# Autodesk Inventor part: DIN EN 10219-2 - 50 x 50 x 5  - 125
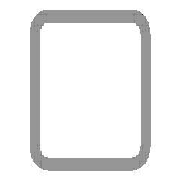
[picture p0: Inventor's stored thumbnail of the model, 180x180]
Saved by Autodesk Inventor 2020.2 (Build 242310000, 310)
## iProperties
Created: 2019-11
Part Number: DIN EN 10219-2 - 50 x 50 x 5  - 125
Material: Generisch
Description: Kaltgeformte, geschweißte Baustahl-Hohlprofile aus unlegiertem Feinkorn-Baustahl
Document SubType Name: Modeling
Standard: DIN
Designer: lutzd
Standard Revision: 2006-07
Standards Organization: DIN
Language: de-DE
Size Designation: 50 x 50 x 5
Categories: <MemberInstance><Categories><Category DisplayName="Profile" InternalName="089c4875-fa83-4c05-b084-43b9cc11f5ed" Mnemonic="GRDR"><CategoryParameter DisplayName="
Stock Number: 50 x 50 x 5
Mass: 104.452 g
Surface Area: 434.522 cm^2
Volume: 104.452 cm^3
Density: 1 g/cm^3
Appearance: Vorgabe
IsCustomPart: 1
_CCFamilyMember: 16
_CCFamilyDisplayName: DIN EN 10219-2 (Quadratisches Hohlprofil - Kaltgeformt) - Kaltgeformte, geschweißte Baustahl-Hohlprofile aus unlegiertem Feinkorn-Baustahl
_FrameMemberDoc: Frame Member File
_Version: 15.0.0
_GetPNFromCC: 1
Title: Profil-Bauteil
Author: lutzd
Revision Number: -
G_L: 125,000 mm
G_W: 50,000 mm
G_H: 50,000 mm
Mass: 0,104 kg
VLT_Material: Generisch
DocNumber: ADSK-014428
Folder: .
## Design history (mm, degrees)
node "Startebene"
node "Endebene"
sketch "Skizze"
  geometry: L1 (-25, -15)-(-25, 15); L2 (-15, 25)-(15, 25); L3 (25, 15)-(25, -15); L4 (15, -25)-(-15, -25); L5 (-15, 20)-(15, 20); L6 (20, 15)-(20, -15); L7 (15, -20)-(-15, -20); L8 (-20, -15)-(-20, 15); L9 (0, 37.899)-(0, -37.899) reference; L10 (-37.899, 0)-(37.899, 0) reference; A1 r 10 centre (-15, -15) between (-25, -15) and (-15, -25); A2 r 10 centre (-15, 15) between (-15, 25) and (-25, 15); A3 r 10 centre (15, 15) between (25, 15) and (15, 25); A4 r 10 centre (15, -15) between (15, -25) and (25, -15); A5 r 5 centre (-15, 15) between (-15, 20) and (-20, 15); A6 r 5 centre (15, 15) between (20, 15) and (15, 20); A7 r 5 centre (15, -15) between (15, -20) and (20, -15); A8 r 5 centre (-15, -15) between (-20, -15) and (-15, -20)
  constraints: 16 end point, 16 point on circle, 8 centre point, 8 tangent, 4 parallel, 3 equal radius, 2 perpendicular, 7 other
  dimensions: "d7" = 10 radius of A1 (= G_IR); "d10" = 50 distance between parallel lines of L2 L4 (= G_H); "d11" = 50 distance between parallel lines of L1 L3 (= G_W); "d12" = 5 distance between parallel lines of L3 L6 (= G_T); "d15" = 25 distance between parallel lines of L2 L10 (= 0.5 x d10); "d16" = 25 distance between parallel lines of L9 L3 (= 0.5 x d11)
extrude "Körper" new body sketch "Skizze" stored distance "d3" = 125 (= G_L); taper "d4" = 0 deg
node "Driven Length"
  sketch "Sketch3"
    geometry: L1 (0, 0)-(10, 0) reference
    constraints: 2 end point, 1 horizontal
  workplane "Work Plane3"
  sketch "Sketch4"
    geometry: L1 (-2, 0)-(12, 0) reference; L2 (-2, 125)-(12, 125) reference
    dimensions: "d18" = 125 distance between parallel lines of L1 L2 (derived)
body "Solid1"
other parameters: "G_W" = 50 [user parameter; used in 1 equation term], "G_H" = 50 [user parameter; used in 1 equation term], "G_T" = 5 [user parameter; used in 1 equation term], "G_IR" = 10 [user parameter; used in 1 equation term], "G_L" = 125 (= d18) [user parameter; used in 1 equation term], "G_OFFSET_START" = 0 [user parameter; used in 1 equation term], "G_OFFSET_END" = 0 [user parameter; used in 1 equation term], "d13" = 0 (computed from G_OFFSET_START), "d14" = 125 (= G_OFFSET_END + B_L), "B_L" = 125 [user parameter; used in 1 equation term], "d17" = 90 deg
